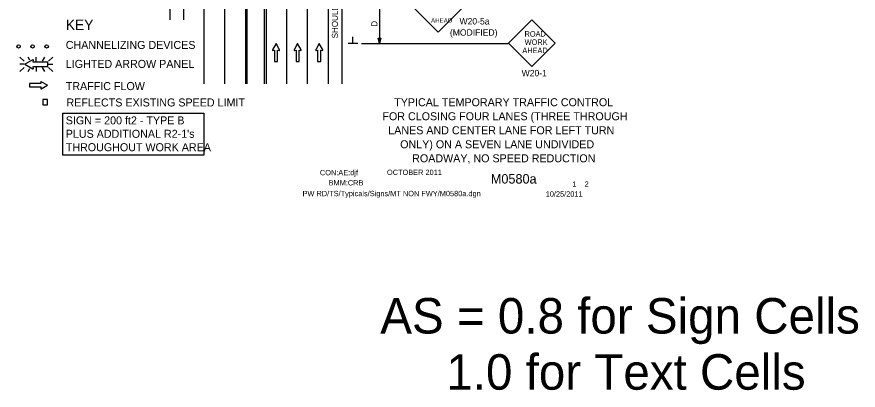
# Model space of a CAD drawing. Extents: x 16732 to 18475, y 6994 to 8262.
# Drawn here: x 16739 to 17716, y 6994 to 7429 of the extents above; entities that cross this region are included whole.
import ezdxf

# ---------------------------------------------------------------- set-up
doc = ezdxf.new("R2010")
doc.units = 0
for name, color, linetype in [('ALI_LEGAL_EX', 7, 'Continuous'), ('BORDER', 7, 'Continuous'), ('BORDER_SIGNAL_WO', 7, 'Continuous'), ('MT_SCRATCH_LEVEL_E', 7, 'Continuous'), ('PAVT_EDGE_EX', 7, 'Continuous'), ('TRAFFIC_SIGNS_PR', 7, 'Continuous'), ('TYPICAL_TEXT_DIMEN_EX', 7, 'Continuous'), ('TYPICAL_TEXT_DIMEN_PR', 7, 'Continuous')]:
    doc.layers.add(name, color=color, linetype=linetype)

msp = doc.modelspace()

# ---------------------------------------------------------------- linework, layer by layer
at = {"layer": 'ALI_LEGAL_EX'}
for p, q in [((16956.31, 7350.48), (16956.31, 8147.76)), ((16980.31, 7350.48), (16980.31, 8147.76)), ((17006.31, 7350.48), (17006.31, 8147.76)), ((17026.31, 7350.48), (17026.31, 8147.76)), ((17052.31, 7350.48), (17052.31, 8147.76)), ((17076.31, 7350.48), (17076.31, 8147.76))]:
    msp.add_line(p, q, dxfattribs=at)
for points in [[(17006.31, 7350.48), (17006.31, 7375.48)], [(17026.31, 7350.48), (17026.31, 7375.48)], [(17052.31, 7350.48), (17052.31, 7375.48)], [(17076.31, 7350.48), (17076.31, 7375.48)]]:
    msp.add_lwpolyline(points, dxfattribs=at)
at = {"layer": 'MT_SCRATCH_LEVEL_E'}
for p, q in [((17039.74, 7397.4), (17035.63, 7390.16)), ((17039.74, 7397.4), (17035.63, 7390.16)), ((17043.89, 7390.16), (17039.74, 7397.4)), ((17043.89, 7390.16), (17039.74, 7397.4)), ((17064.83, 7397.4), (17060.72, 7390.16)), ((17064.83, 7397.4), (17060.72, 7390.16)), ((17068.98, 7390.16), (17064.83, 7397.4)), ((17068.98, 7390.16), (17064.83, 7397.4)), ((17089.92, 7397.4), (17085.81, 7390.16)), ((17089.92, 7397.4), (17085.81, 7390.16)), ((17094.07, 7390.16), (17089.92, 7397.4)), ((17094.07, 7390.16), (17089.92, 7397.4)), ((17036.12, 7389.48), (17037.89, 7389.79)), ((17036.12, 7389.48), (17037.89, 7389.79)), ((17037.89, 7389.79), (17037.89, 7376.54)), ((17037.89, 7389.79), (17037.89, 7376.54)), ((17041.63, 7376.54), (17041.63, 7389.79)), ((17041.63, 7389.79), (17043.41, 7389.48)), ((17041.63, 7376.54), (17041.63, 7389.79)), ((17041.63, 7389.79), (17043.41, 7389.48)), ((17061.2, 7389.48), (17062.98, 7389.79)), ((17061.2, 7389.48), (17062.98, 7389.79)), ((17062.98, 7389.79), (17062.98, 7376.54)), ((17062.98, 7389.79), (17062.98, 7376.54)), ((17066.72, 7376.54), (17066.72, 7389.79)), ((17066.72, 7389.79), (17068.5, 7389.48)), ((17066.72, 7376.54), (17066.72, 7389.79)), ((17066.72, 7389.79), (17068.5, 7389.48)), ((17086.29, 7389.48), (17088.07, 7389.79)), ((17086.29, 7389.48), (17088.07, 7389.79)), ((17088.07, 7389.79), (17088.07, 7376.54)), ((17088.07, 7389.79), (17088.07, 7376.54)), ((17091.81, 7376.54), (17091.81, 7389.79)), ((17091.81, 7389.79), (17093.59, 7389.48)), ((17091.81, 7376.54), (17091.81, 7389.79)), ((17091.81, 7389.79), (17093.59, 7389.48)), ((17037.89, 7376.54), (17041.63, 7376.54)), ((17037.89, 7376.54), (17041.63, 7376.54)), ((17062.98, 7376.54), (17066.72, 7376.54)), ((17062.98, 7376.54), (17066.72, 7376.54)), ((17088.07, 7376.54), (17091.81, 7376.54)), ((17088.07, 7376.54), (17091.81, 7376.54)), ((16766.74, 7350.85), (16753.48, 7350.85)), ((16753.48, 7350.85), (16753.48, 7347.11)), ((16766.74, 7350.85), (16753.48, 7350.85)), ((16753.48, 7350.85), (16753.48, 7347.11)), ((16766.43, 7352.63), (16766.74, 7350.85)), ((16766.43, 7352.63), (16766.74, 7350.85)), ((16774.35, 7349), (16767.11, 7353.11)), ((16774.35, 7349), (16767.11, 7353.11)), ((16767.11, 7344.85), (16774.35, 7349)), ((16767.11, 7344.85), (16774.35, 7349)), ((16753.48, 7347.11), (16766.74, 7347.11)), ((16753.48, 7347.11), (16766.74, 7347.11)), ((16766.74, 7347.11), (16766.43, 7345.33)), ((16766.74, 7347.11), (16766.43, 7345.33))]:
    msp.add_line(p, q, dxfattribs=at)
for centre, start, end in [((17036.04, 7389.94), 150.42484, 279.96381), ((17036.04, 7389.94), 150.42484, 279.96381), ((17043.48, 7389.94), 260.03619, 29.77312), ((17043.48, 7389.94), 260.03619, 29.77312), ((17061.13, 7389.94), 150.42484, 279.96381), ((17061.13, 7389.94), 150.42484, 279.96381), ((17068.57, 7389.94), 260.03619, 29.77312), ((17068.57, 7389.94), 260.03619, 29.77312), ((17086.22, 7389.94), 150.42484, 279.96381), ((17086.22, 7389.94), 150.42484, 279.96381), ((17093.66, 7389.94), 260.03619, 29.77312), ((17093.66, 7389.94), 260.03619, 29.77312), ((16766.89, 7352.7), 60.42484, 189.96381), ((16766.89, 7352.7), 60.42484, 189.96381), ((16766.89, 7345.26), 170.03619, 299.77312), ((16766.89, 7345.26), 170.03619, 299.77312)]:
    msp.add_arc(centre, 0.463, start, end, dxfattribs=at)
at = {"layer": 'PAVT_EDGE_EX'}
for p, q in [((16916.31, 8206.5), (16916.31, 7425.05)), ((16932.31, 8206.5), (16932.31, 7425.05)), ((17004.31, 8206.5), (17004.31, 7350.48)), ((17028.31, 8206.5), (17028.31, 7350.48)), ((17100.31, 8206.5), (17100.31, 7350.48)), ((17116.31, 8206.5), (17116.31, 7350.48))]:
    msp.add_line(p, q, dxfattribs=at)
at = {"layer": 'TRAFFIC_SIGNS_PR'}
for p, q in [((17201, 7437.82), (17228.16, 7410.67)), ((17228.16, 7410.67), (17255.31, 7437.82)), ((17336.83, 7425.15), (17309.68, 7398)), ((17363.98, 7398), (17336.83, 7425.15)), ((17309.68, 7398), (17336.83, 7370.85)), ((17336.83, 7370.85), (17363.98, 7398)), ((16742.22, 7381.8), (16747.15, 7376.87)), ((16753.98, 7377.98), (16751.77, 7381.8)), ((16761.3, 7376.87), (16761.3, 7381.8)), ((16768.53, 7376.87), (16771.38, 7381.8)), ((16775.45, 7376.87), (16780.38, 7381.81)), ((16747.15, 7373.31), (16742.22, 7373.31)), ((16742.22, 7364.83), (16747.15, 7369.76)), ((16751.73, 7364.82), (16753.84, 7368.49)), ((16761.3, 7369.76), (16761.3, 7364.82)), ((16771.43, 7364.82), (16768.58, 7369.76)), ((16775.45, 7373.31), (16780.38, 7373.31)), ((16775.45, 7369.76), (16780.38, 7364.82))]:
    msp.add_line(p, q, dxfattribs=at)
for points in [[(16757.23, 7378.59), (16747.93, 7373.31), (16757.23, 7367.99)], [(16758.1, 7368.62), (16757.7, 7370.89), (16774.71, 7370.89), (16774.71, 7375.69), (16757.7, 7375.69), (16758.1, 7377.97)]]:
    msp.add_lwpolyline(points, dxfattribs=at)
msp.add_lwpolyline([(16768.76, 7326.15), (16774.35, 7326.15), (16774.35, 7332.32), (16768.76, 7332.32)], close=True, dxfattribs=at)
for centre in [(16740.73, 7394.15), (16757.03, 7394.15), (16773.33, 7394.15)]:
    msp.add_circle(centre, 2, dxfattribs=at)
for centre, radius, start, end in [((16757.51, 7378.07), 0.598, 350.73078, 118.89165), ((16757.51, 7368.52), 0.597, 241.48329, 9.95933)]:
    msp.add_arc(centre, radius, start, end, dxfattribs=at)
at = {"layer": 'TYPICAL_TEXT_DIMEN_EX'}
msp.add_lwpolyline([(16792.23, 7316.59), (16955.75, 7316.59), (16955.75, 7267.72), (16792.23, 7267.72)], close=True, dxfattribs=at)
at = {"layer": 'TYPICAL_TEXT_DIMEN_PR'}
for p, q in [((17159.94, 7437.69), (17159.94, 7397.69)), ((17134.69, 7397.69), (17123.44, 7397.69)), ((17129.06, 7397.69), (17129.06, 7405.48)), ((17138.94, 7397.69), (17309.22, 7397.69)), ((17159.94, 7397.69), (17158.37, 7403.55)), ((17158.37, 7403.55), (17159.94, 7403.55)), ((17159.94, 7403.55), (17161.51, 7403.55)), ((17161.51, 7403.55), (17159.94, 7397.69))]:
    msp.add_line(p, q, dxfattribs=at)

# ---------------------------------------------------------------- texts
at = {"layer": 'BORDER'}
for s, p in [('TYPICAL TEMPORARY TRAFFIC CONTROL', (17177.02, 7324.57)), ('FOR CLOSING FOUR LANES (THREE THROUGH', (17163.29, 7308.27)), ('LANES AND CENTER LANE FOR LEFT TURN', (17170.07, 7291.97)), ('ONLY) ON A SEVEN LANE UNDIVIDED', (17183.91, 7275.67)), ('ROADWAY, NO SPEED REDUCTION', (17197.83, 7259.37))]:
    msp.add_text(s, height=9.3, dxfattribs=at).set_placement(p)
at = {"layer": 'BORDER_SIGNAL_WO'}
for s, height, p in [('CON:AE:djf', 6.2, (17090.69, 7244.31)), ('    OCTOBER 2011    ', 6.2, (17159.08, 7244.59)), ('    M0580a   ', 11, (17272.86, 7234.63)), ('BMM:CRB   ', 6.2, (17100.81, 7232.42)), (' 1    2 ', 6.2, (17381.45, 7230.95)), ('PW RD/TS/Typicals/Signs/MT NON FWY/M0580a.dgn     ', 6.2, (17070.55, 7219.96)), ('10/25/2011    ', 6.2, (17352.93, 7219.38)), ('AS = 0.8 for Sign Cells', 41.2877, (17160.83, 7060.19)), ('     1.0 for Text Cells', 41.2877, (17160.83, 6994.91))]:
    msp.add_text(s, height=height, dxfattribs=at).set_placement(p)
at = {"layer": 'TRAFFIC_SIGNS_PR'}
for s, height, p in [('W20-5a', 7.44, (17252.83, 7419.67)), ('(MODIFIED)', 7.44, (17241.68, 7406.63)), ('ROAD', 6.4, (17328.37, 7405.53)), ('WORK', 6.4, (17328.48, 7395.93)), ('AHEAD', 6.4, (17325.79, 7386.33)), ('W20-1', 7.44, (17325, 7359.41))]:
    msp.add_text(s, height=height, dxfattribs=at).set_placement(p)
at = {"layer": 'TYPICAL_TEXT_DIMEN_EX'}
for s, height, p in [('KEY', 12, (16795.56, 7413.26)), ('CHANNELIZING DEVICES', 9.3, (16795.56, 7391.21)), ('LIGHTED ARROW PANEL', 9.3, (16795.56, 7369.16)), ('TRAFFIC FLOW', 9.3, (16795.56, 7343.36)), ('REFLECTS EXISTING SPEED LIMIT', 9.3, (16796.38, 7324.31)), ('SIGN = 200 ft2 - TYPE B', 9.3, (16795.56, 7303.47)), ("PLUS ADDITIONAL R2-1's", 9.3, (16795.56, 7287.87)), ('THROUGHOUT WORK AREA', 9.3, (16795.56, 7272.27))]:
    msp.add_text(s, height=height, dxfattribs=at).set_placement(p)
at = {"layer": 'TYPICAL_TEXT_DIMEN_PR'}
for s, p in [('SHOULDER', (17111.59, 7403.51)), ('D', (17157.38, 7417.05))]:
    msp.add_text(s, height=7, rotation=90, dxfattribs=at).set_placement(p)
msp.add_text('AHEAD', height=5.2, dxfattribs=at).set_placement((17219.76, 7421.63))

doc.saveas('drawing.dxf')
